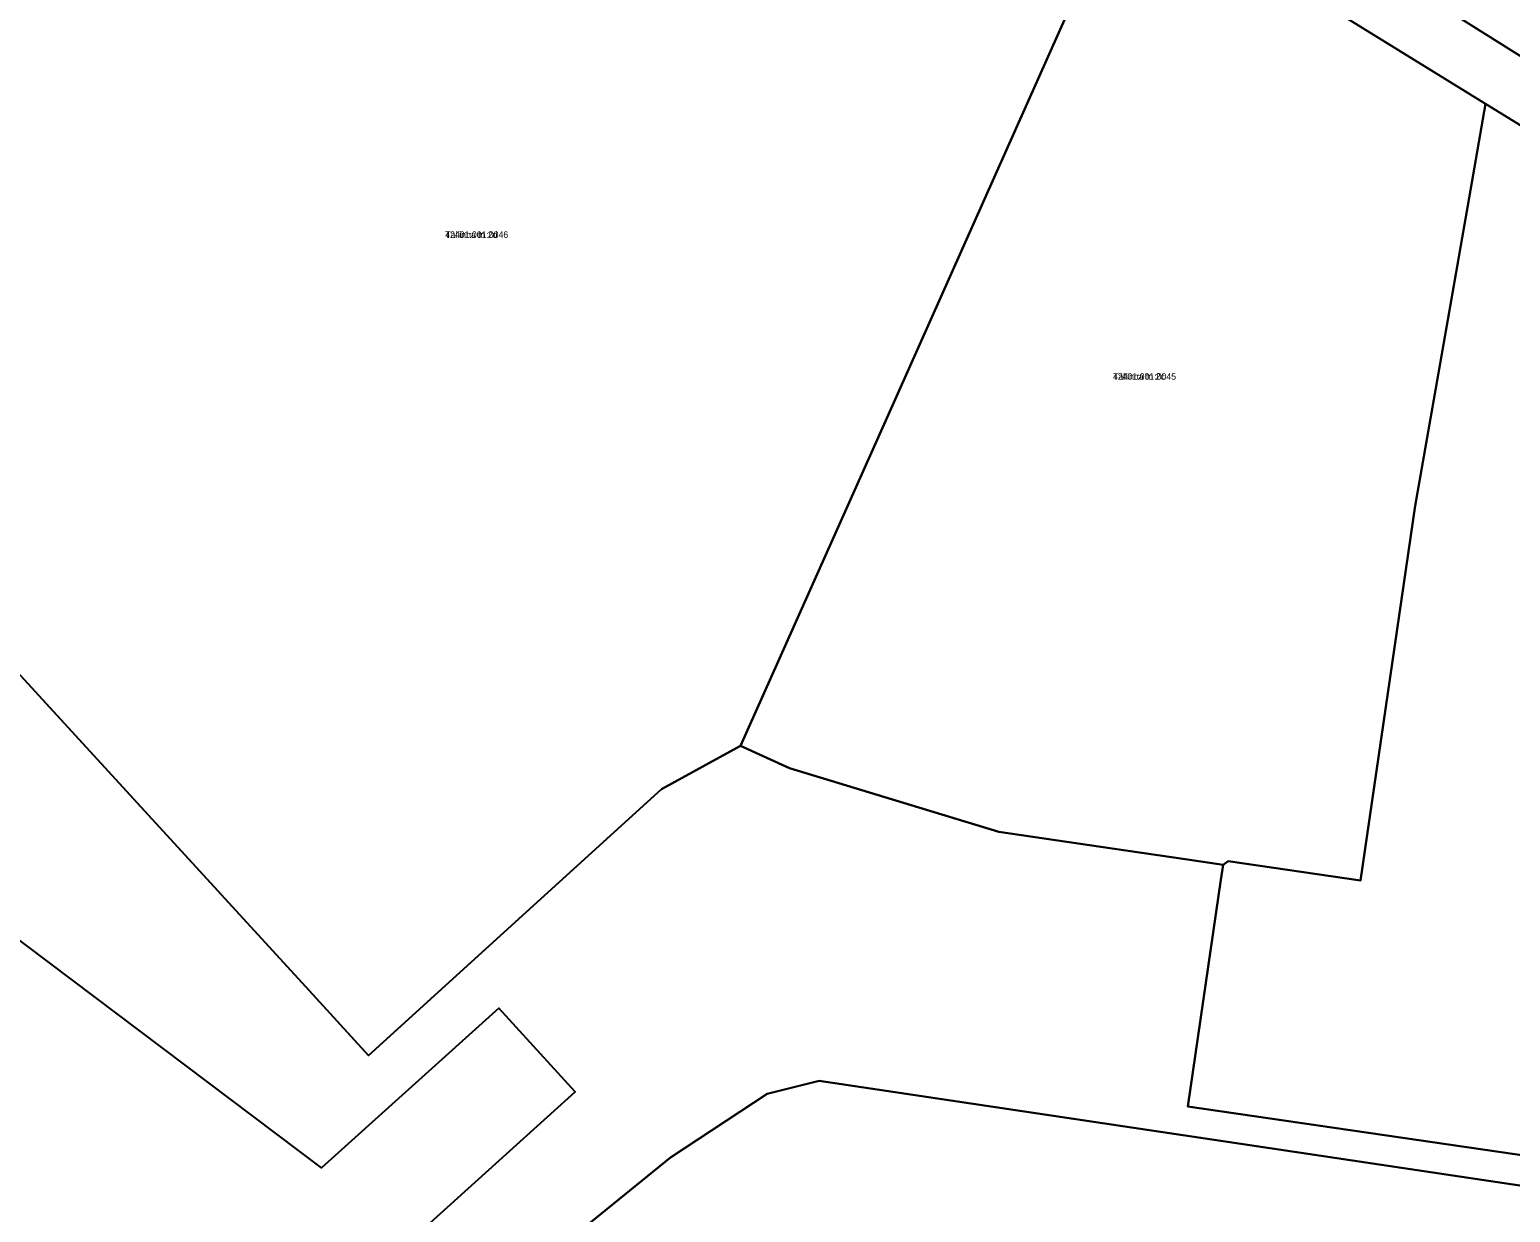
# Model space of a CAD drawing. Extents: x 595979 to 597983, y 6604231 to 6607350.
# Drawn here: x 596303.1 to 596644, y 6606340.2 to 6606612.5 of the extents above; entities that cross this region are included whole.
import ezdxf

# ---------------------------------------------------------------- set-up
doc = ezdxf.new("R2010")
doc.units = 0
for name, color, linetype in [('L_AADRESS', 7, 'Continuous'), ('PIIR', 7, 'Continuous'), ('TUNNUS', 7, 'Continuous')]:
    doc.layers.add(name, color=color, linetype=linetype)

msp = doc.modelspace()

# ---------------------------------------------------------------- linework, layer by layer
at = {"layer": 'PIIR'}
for points in [[(596909.1, 6606385.61), (596872.46, 6606418.2), (596861.56, 6606419.99), (596848.55, 6606432.38), (596762.79, 6606514.09), (596675.69, 6606572.34), (596638.27, 6606595.39), (596557.11, 6606645.51), (596555.44, 6606646.42), (596542.85, 6606653.57), (596526.52, 6606663), (596451.2, 6606705.15), (596442.76, 6606730.14), (596437.35, 6606745.96), (596437.73, 6606810.5), (596437.33, 6606810.61), (596437.96, 6606836.91), (596442.64, 6606872.04), (596470.43, 6606959.84)], [(596464.47, 6606887.4), (596457.38, 6606863.19), (596452.59, 6606835.16), (596451.96, 6606809.89), (596451.4, 6606745.94), (596455.33, 6606728.96), (596461.16, 6606718.64), (596465.96, 6606712.4), (596556.83, 6606658.51), (596558.45, 6606661.57), (596684.47, 6606582.41), (596720.93, 6606558.63), (596736.24, 6606555.98), (596767.98, 6606529.52), (596797.47, 6606504.22), (596834.39, 6606472.9), (596889.22, 6606422.58)], [(596242.07, 6606528), (596367.46, 6606391.27), (596381.08, 6606376.31), (596448.58, 6606437.61), (596466.73, 6606447.57), (596477.99, 6606442.43), (596526.21, 6606427.77), (596552.3, 6606423.95), (596569.63, 6606421.41), (596577.86, 6606420.2), (596577.35, 6606416.75), (596569.74, 6606364.59), (596720.28, 6606342.66), (596739.8, 6606366.49), (596737.8, 6606352.55), (596723.23, 6606334.88), (596484.87, 6606370.45), (596472.89, 6606367.48), (596450.64, 6606352.84), (596418.86, 6606327.05)], [(596240.87, 6606223.87), (596359.28, 6606217.55), (596369.33, 6606223.32), (596394.85, 6606282.83), (596381.06, 6606289.09), (596395.45, 6606321.82), (596388.17, 6606331.38), (596428.65, 6606367.99), (596411.06, 6606387.25), (596370.24, 6606350.47), (596276.09, 6606421.39)], [(596418.86, 6606327.05), (596450.64, 6606352.84), (596472.89, 6606367.48), (596484.87, 6606370.45), (596723.23, 6606334.88)]]:
    msp.add_lwpolyline(points, dxfattribs=at)
for points in [[(596370.72, 6606652.99), (596397.75, 6606736.83), (596419.38, 6606733.61), (596442.76, 6606730.14), (596451.2, 6606705.15), (596526.52, 6606663), (596515.45, 6606641.74), (596515.49, 6606628.51), (596528, 6606622.65), (596542.08, 6606651.96), (596542.85, 6606653.57), (596555.44, 6606646.42), (596540.01, 6606611.84), (596500.4, 6606523.05), (596466.73, 6606447.57), (596448.58, 6606437.61), (596381.08, 6606376.31), (596367.46, 6606391.27), (596242.07, 6606528), (596288.27, 6606678.52)], [(596733.13, 6606656.54), (596684.47, 6606582.41), (596558.45, 6606661.57), (596566.37, 6606676.82), (596606.42, 6606693.19), (596663.04, 6606703.09), (596708.41, 6606673.12)], [(596540.01, 6606611.84), (596555.44, 6606646.42), (596557.11, 6606645.51), (596638.27, 6606595.39), (596634.48, 6606573.71), (596630.11, 6606548.73), (596622.09, 6606502.86), (596609.49, 6606416.58), (596578.99, 6606421.05), (596577.86, 6606420.2), (596569.63, 6606421.41), (596552.3, 6606423.95), (596526.21, 6606427.77), (596477.99, 6606442.43), (596466.73, 6606447.57), (596500.4, 6606523.05)], [(596634.48, 6606573.71), (596638.27, 6606595.39), (596675.69, 6606572.34), (596762.79, 6606514.09), (596848.55, 6606432.38), (596831.88, 6606435.78), (596800.52, 6606462.81), (596786.69, 6606477.58), (596763.58, 6606493.7), (596758.19, 6606494.47), (596739.8, 6606366.49), (596720.28, 6606342.66), (596569.74, 6606364.59), (596577.35, 6606416.75), (596577.86, 6606420.2), (596578.99, 6606421.05), (596609.49, 6606416.58), (596622.09, 6606502.86), (596630.11, 6606548.73)]]:
    msp.add_lwpolyline(points, close=True, dxfattribs=at)

# ---------------------------------------------------------------- texts
at = {"layer": 'L_AADRESS'}
for s, p in [('Tallinna tn 2d', (596398.75, 6606564.52)), ('Tallinna tn 2c', (596552.5, 6606531.88))]:
    msp.add_text(s, height=1.5, dxfattribs=at).set_placement(p)
at = {"layer": 'TUNNUS'}
for s, p in [('42401:001:0046', (596398.75, 6606564.52)), ('42401:001:0045', (596552.5, 6606531.88))]:
    msp.add_text(s, height=1.5, dxfattribs=at).set_placement(p)

doc.saveas('drawing.dxf')
